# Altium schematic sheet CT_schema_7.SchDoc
size 277 x 170 mm
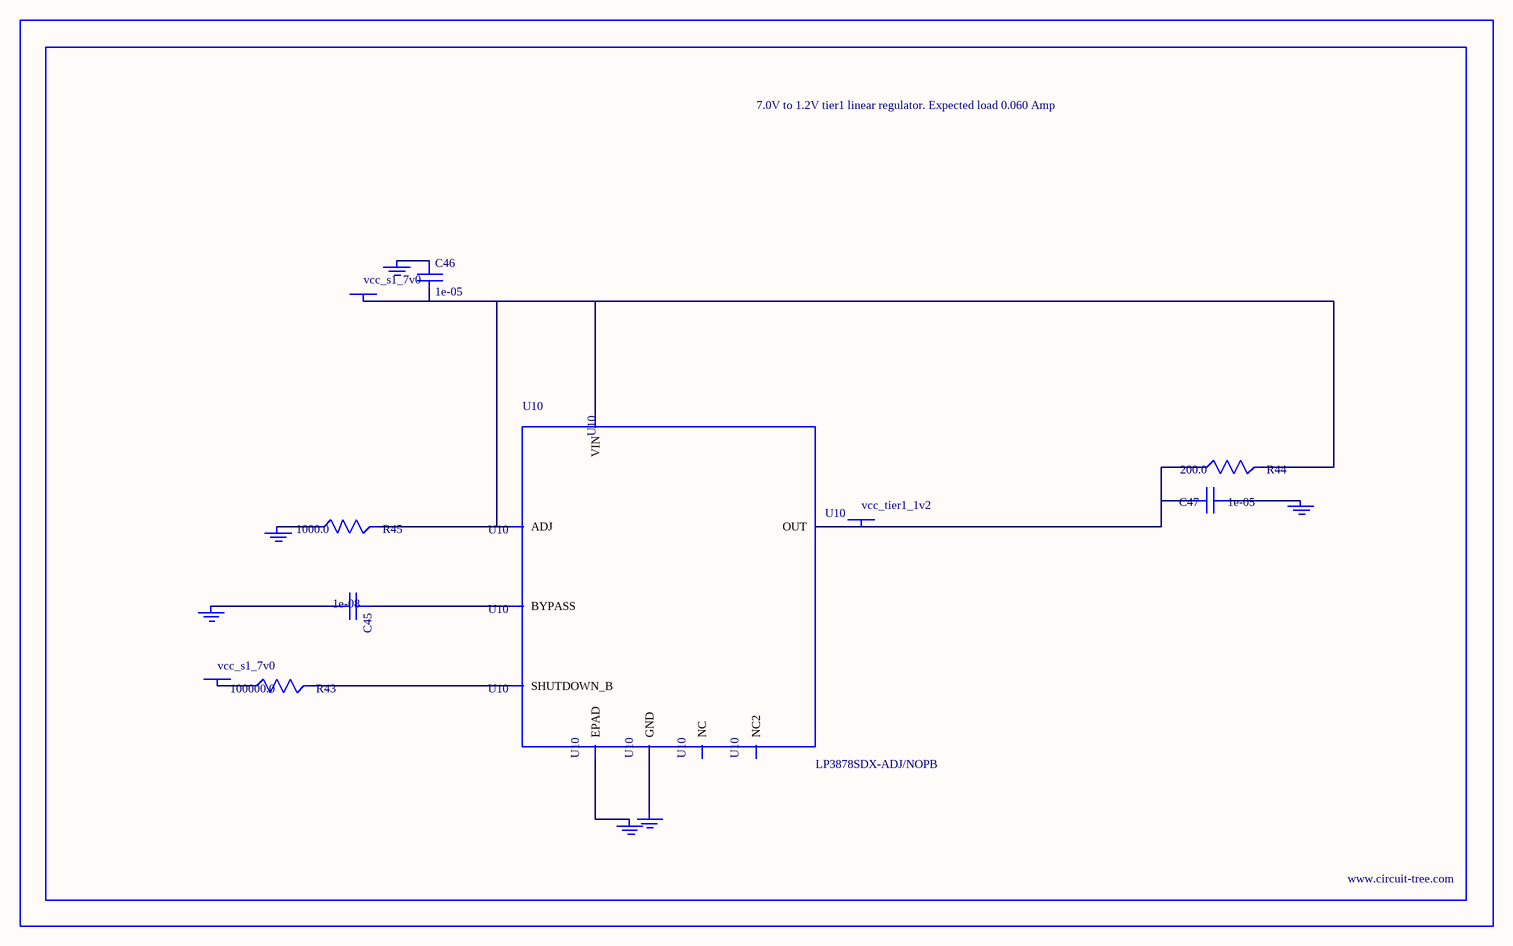
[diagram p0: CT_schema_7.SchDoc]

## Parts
BORDER6  (no value)
C45  1e-08  [C0402]
C46  1e-05  [C1206]
C47  1e-05  [C0805]
GND_INSTANCE_6_0  (no value)
GND_INSTANCE_6_1  (no value)
GND_INSTANCE_6_2  (no value)
GND_INSTANCE_6_3  (no value)
GND_INSTANCE_6_4  (no value)
GND_INSTANCE_6_5  (no value)
POWER_INSTANCE_6_0  vcc_s1_7v0
POWER_INSTANCE_6_1  vcc_s1_7v0
POWER_INSTANCE_6_2  vcc_tier1_1v2
R43  100000.0  [R0603]
R44  200.0  [R0603]
R45  1000.0  [R0603]
U10  LP3878SDX-ADJ/NOPB  [WSON-8]

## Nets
NetC45_1: C45.1 U10.1(BYPASS)
NetC45_2: C45.2 GND_INSTANCE_6_0.0(GND)
NetC46_1: C46.1 GND_INSTANCE_6_1.0(GND)
NetC46_2: C46.2 POWER_INSTANCE_6_0.0(PWR) R44.2 R45.2 U10.4(VIN) U10.6(ADJ)
NetC47_1: C47.1 GND_INSTANCE_6_2.0(GND)
NetC47_2: C47.2 POWER_INSTANCE_6_2.0(PWR) R44.1 U10.5(OUT)
NetGND_INSTANCE_6_3_0: GND_INSTANCE_6_3.0(GND) R45.1
NetGND_INSTANCE_6_4_0: GND_INSTANCE_6_4.0(GND) U10.PAD(EPAD)
NetGND_INSTANCE_6_5_0: GND_INSTANCE_6_5.0(GND) U10.3(GND)
NetPOWER_INSTANCE_6_1_0: POWER_INSTANCE_6_1.0(PWR) R43.1
NetR43_2: R43.2 U10.8(SHUTDOWN_B)

Not connected (* = marked no-connect by the designer): U10 2(NC) 7(NC2)

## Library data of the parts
BORDER6 = BORDER_PAGE6
C45 = C0402C103K3RAC
C46 = C1206C106K3RACTU
C47 = GRM219R60J106ME19D
GND_INSTANCE_6_0-GND_INSTANCE_6_5 = GND
POWER_INSTANCE_6_0-POWER_INSTANCE_6_2 = PWR
R43 = RC0603JR-07100KL
R44 = RC0603JR-07200RL
R45 = RC0603JR-071KL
